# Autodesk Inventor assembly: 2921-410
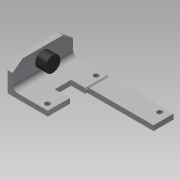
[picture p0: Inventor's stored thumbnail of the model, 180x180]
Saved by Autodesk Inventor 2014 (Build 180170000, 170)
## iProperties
Company: NHTSA/VRTC
Created: 2012-08
Part Number: 2921-410
Document SubType Name: Weldment
Designer: Mike Vanvoorhis
Weld Material: Welded Steel Mild
Mass: 424.973 g
Surface Area: 825.087 cm^2
Volume: 417.508 cm^3
Density: 1.01788 g/cm^3
Project: CHILD SIDE IMPACT SLED
Description: LEFT SIDE BUMPER ASSEMBLY
Author: Dave Walker
Title: Left Side Bumper Assembly
Subject: Child Side Impact Sled
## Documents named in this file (4)
- B:\VRTC_DWG\BIO\Non-P572\Child Side-Frontal Impact Sled\Side Impact Sled\LeftSide_Bumper.iam
- B:\VRTC_DWG\BIO\Non-P572\Child Side-Frontal Impact Sled\Side Impact Sled\Bumper_Base_Extension.ipt
- B:\VRTC_DWG\BIO\Non-P572\Child Side-Frontal Impact Sled\Side Impact Sled\Bumper_Base.ipt
- B:\VRTC_DWG\BIO\Non-P572\Child Side-Frontal Impact Sled\Side Impact Sled\Bumper.iam
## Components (3 placed, 3 different names)
1. Bumper_Base:1 — Mate:3, Insert:1, Flush:4, Flush:5
2. Bumper:2 [sub-assembly] — Insert:1
3. Bumper_Base_Extension:1 — Mate:3, Flush:4, Flush:5
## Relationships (4: Flush 2, Mate 1, Insert 1)
- Mate:3: Bumper_Base:1 ↔ Bumper_Base_Extension:1
- Insert:1: Bumper_Base:1 ↔ Bumper:2
- Flush:4: Bumper_Base:1 ↔ Bumper_Base_Extension:1
- Flush:5: Bumper_Base:1 ↔ Bumper_Base_Extension:1
